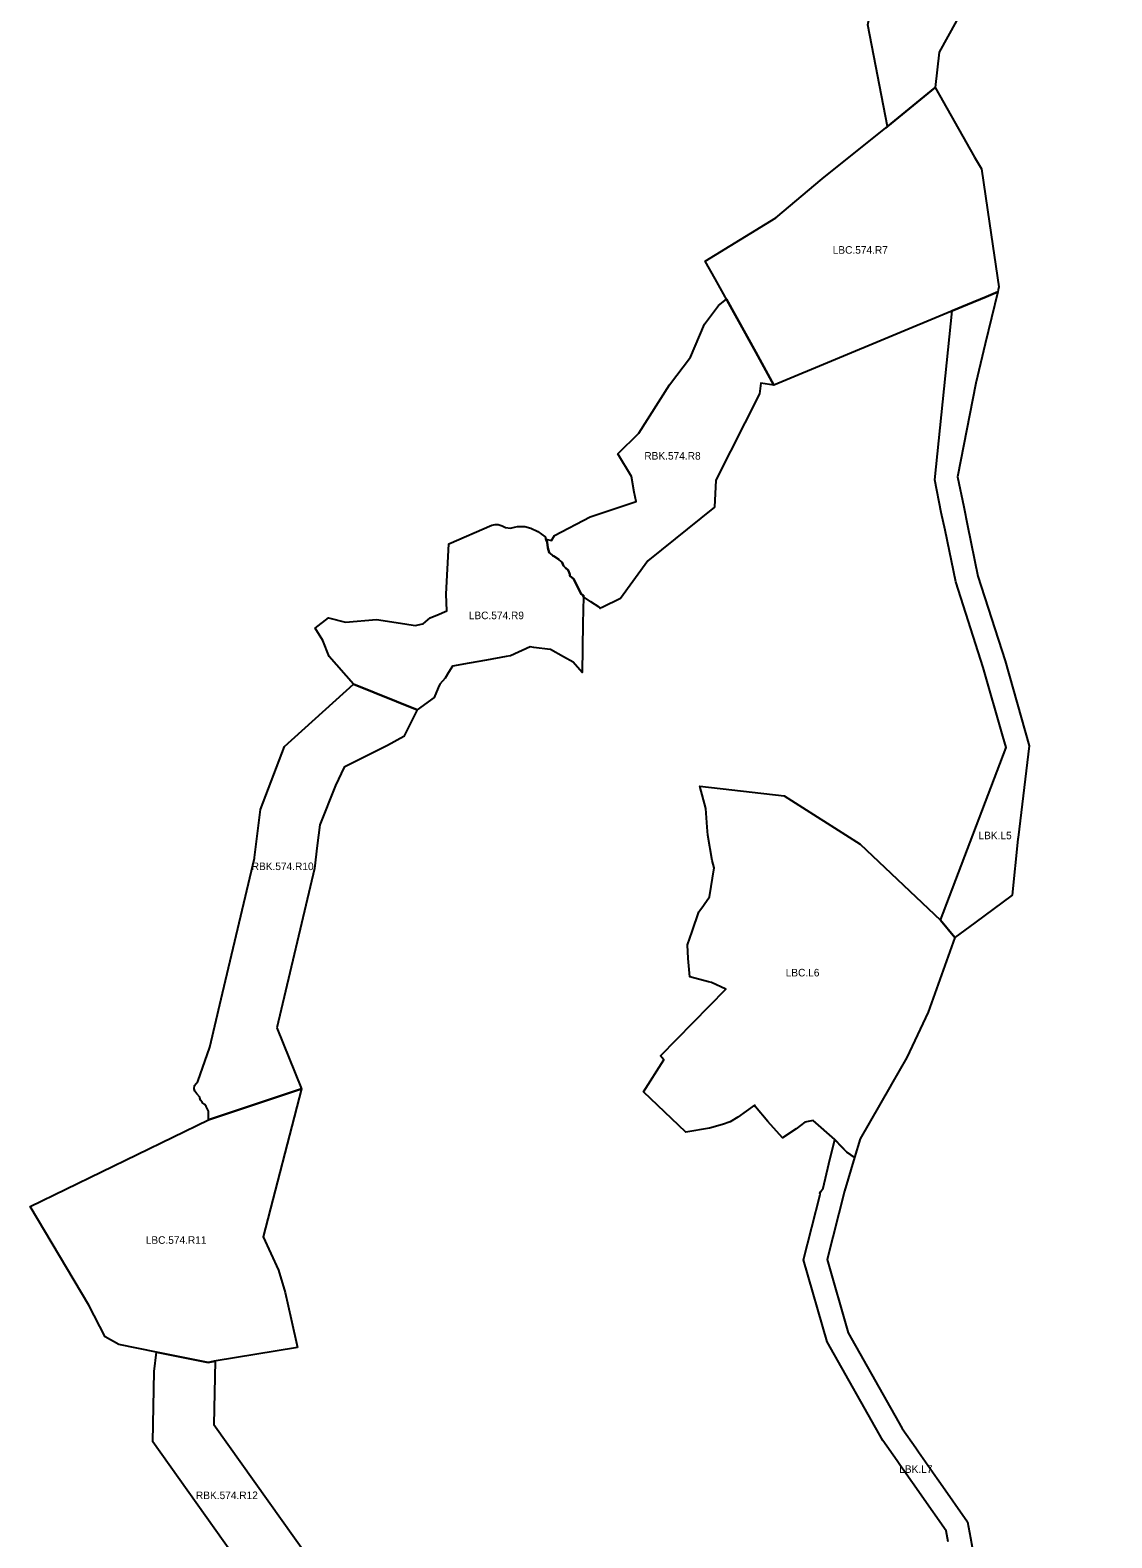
# Model space of a CAD drawing. Extents: x -450188 to -432919, y -1130252 to -1121189.
# Drawn here: x -435713 to -434285, y -1125455 to -1123464 of the extents above; entities that cross this region are included whole.
import ezdxf

# ---------------------------------------------------------------- set-up
doc = ezdxf.new("R2010")
doc.units = 0
for name, color, linetype in [('Vrstva 31', 7, 'Continuous'), ('Vrstva 32', 7, 'Continuous'), ('Vrstva 33', 7, 'Continuous'), ('Vrstva 36', 7, 'Continuous')]:
    doc.layers.add(name, color=color, linetype=linetype)

msp = doc.modelspace()

# ---------------------------------------------------------------- linework, layer by layer
at = {"layer": 'Vrstva 31'}
for p, q in [((-434518, -1123539.7), (-434580.6, -1123591.5)), ((-435286, -1124327.5), (-435201.7, -1124361.3)), ((-435546.1, -1125209.4), (-435477.7, -1125222.9))]:
    msp.add_line(p, q, dxfattribs=at)
for points in [[(-434363.9, -1123020.8), (-434324.5, -1123013.7), (-434284.6, -1123005.4), (-434295.7, -1123018.7), (-434299.7, -1123028.1), (-434301.1, -1123031.3), (-434304.3, -1123038.5), (-434314.4, -1123051.7), (-434320.8, -1123078.5), (-434332, -1123096.3), (-434354, -1123131.2), (-434377.2, -1123169.1), (-434389.6, -1123189.4), (-434412.9, -1123227.4), (-434449.8, -1123301), (-434458.9, -1123351.3), (-434471.9, -1123405.2), (-434478.2, -1123431.2), (-434512.4, -1123493.4), (-434518, -1123539.7)], [(-434580.6, -1123591.5), (-434606.8, -1123457.2), (-434543.2, -1123160.2), (-434507.9, -1123124.6), (-434478.5, -1123094.9), (-434447.2, -1123063.3), (-434413.4, -1123029.2)], [(-435387.2, -1124781.1), (-435354.5, -1124861.6), (-435477.4, -1124902.8), (-435477.4, -1124891.1), (-435480.1, -1124885), (-435482.1, -1124882.6), (-435485.2, -1124880.1), (-435485.6, -1124879.6), (-435487.6, -1124876.7), (-435488.5, -1124873.7), (-435488.8, -1124872.7), (-435492.5, -1124868.4), (-435495.1, -1124865), (-435496, -1124861.8), (-435495.5, -1124857.5), (-435491.3, -1124852.1), (-435475.5, -1124806.7), (-435460.4, -1124743), (-435458.7, -1124735.5), (-435416.6, -1124557.3), (-435416.4, -1124556.6), (-435408.4, -1124493), (-435376.7, -1124410), (-435286, -1124327.5)], [(-435201.7, -1124361.3), (-435219.3, -1124396.7), (-435241, -1124408.4), (-435298, -1124437.1), (-435309.5, -1124461.4), (-435330.3, -1124513.2), (-435333.8, -1124540.7), (-435337.5, -1124570.8), (-435387.2, -1124781.1)], [(-435477.7, -1125222.9), (-435468.6, -1125221.4), (-435470.4, -1125304.9), (-435345.1, -1125480.7), (-435258.9, -1125531.3), (-435353.4, -1125573.9), (-435398.3, -1125542.3), (-435550.8, -1125327.8), (-435548.9, -1125234.9), (-435546.1, -1125209.4)]]:
    msp.add_lwpolyline(points, dxfattribs=at)
msp.add_lwpolyline([(-435031.7, -1124136), (-435024.3, -1124138.1), (-435020.3, -1124131.1), (-434973.2, -1124106.6), (-434912.7, -1124086.2), (-434915.1, -1124074.2), (-434918.7, -1124053.4), (-434936.9, -1124023.5), (-434909, -1123996.3), (-434868.8, -1123932.3), (-434841, -1123895.9), (-434822.5, -1123852.2), (-434804, -1123827.8), (-434793.3, -1123819.1), (-434754.4, -1123889.2), (-434730.8, -1123932.7), (-434748, -1123930.1), (-434749.6, -1123944.2), (-434807.3, -1124058.1), (-434809.2, -1124093.7), (-434897, -1124164.8), (-434933.1, -1124214.3), (-434957.5, -1124226.2), (-434959.7, -1124227.3), (-434960.3, -1124227.6), (-434961.4, -1124225.8), (-434972.3, -1124218.8), (-434982.2, -1124212.3), (-434983, -1124209.5), (-434984.6, -1124209), (-434995.4, -1124188.5), (-435000.3, -1124184.4), (-435000.3, -1124182.2), (-435002.4, -1124177.2), (-435005.9, -1124174.1), (-435008.4, -1124171.3), (-435010.1, -1124166.9), (-435015.3, -1124162.7), (-435021.5, -1124158.7), (-435027.6, -1124153.9), (-435029.4, -1124147.6), (-435030.2, -1124139.9)], close=True, dxfattribs=at)
at = {"layer": 'Vrstva 32'}
for p, q in [((-434580.6, -1123591.5), (-434518, -1123539.7)), ((-434583, -1123593.5), (-434580.6, -1123591.6)), ((-434580.6, -1123591.6), (-434580.6, -1123591.5)), ((-435005.9, -1124174.1), (-435002.4, -1124177.2)), ((-435002.4, -1124177.2), (-435000.6, -1124181.5)), ((-435000.6, -1124181.5), (-435000.3, -1124182.2)), ((-434984.6, -1124209), (-434983, -1124209.5)), ((-434983, -1124209.5), (-434982, -1124210)), ((-435201.7, -1124361.3), (-435286, -1124327.5)), ((-434511, -1124639.1), (-434491.8, -1124662.2)), ((-434643.1, -1124936.6), (-434650.5, -1124928.8))]:
    msp.add_line(p, q, dxfattribs=at)
for points in [[(-434518, -1123539.7), (-434465.7, -1123631.7), (-434456.8, -1123647.3), (-434445.9, -1123719.6), (-434433.6, -1123802.9), (-434434.6, -1123807.1), (-434435.2, -1123809.7)], [(-434808.4, -1123792.6), (-434821.5, -1123769.2), (-434728.1, -1123712.1), (-434666.9, -1123660.3), (-434580.6, -1123591.5), (-434583, -1123593.5)], [(-434730.8, -1123932.7), (-434754.4, -1123889.2), (-434808.4, -1123792.6)], [(-434435.2, -1123809.7), (-434450.3, -1123816), (-434475.1, -1123826.3)], [(-434475.1, -1123826.3), (-434495.6, -1123834.8), (-434497.3, -1123835.5), (-434730.8, -1123932.7)], [(-435286, -1124327.5), (-435317.7, -1124291.1), (-435317.7, -1124290.9), (-435326.2, -1124270), (-435336.5, -1124253.5), (-435318.9, -1124240.1), (-435296.4, -1124245.8), (-435255.4, -1124242.4), (-435218.1, -1124247.9), (-435204.4, -1124249.9), (-435194.4, -1124248.1), (-435193.6, -1124247.9), (-435184.4, -1124240.2), (-435172.9, -1124235.2), (-435165.6, -1124231.9), (-435162.6, -1124230.6), (-435163.5, -1124208.7), (-435159.8, -1124142.3), (-435103, -1124117.7), (-435098.9, -1124116.8), (-435094.7, -1124116.8), (-435089.6, -1124118.6), (-435085, -1124120.7), (-435078.6, -1124121.5), (-435073.4, -1124120.2), (-435069.2, -1124119.6), (-435067.1, -1124119.3), (-435060.9, -1124119.3), (-435059.4, -1124119.3), (-435051.8, -1124121.6), (-435042.4, -1124126.2), (-435032.9, -1124132.9), (-435031.7, -1124136)], [(-435031.7, -1124136), (-435030.2, -1124139.9), (-435029.4, -1124147.6), (-435027.6, -1124153.9)], [(-435027.6, -1124153.9), (-435022.9, -1124157.8), (-435021.5, -1124158.7), (-435015.3, -1124162.7), (-435014.5, -1124163.4)], [(-435014.5, -1124163.4), (-435010.1, -1124166.9), (-435008.4, -1124171.3), (-435005.9, -1124174.1)], [(-435000.3, -1124182.2), (-435000.3, -1124184.4), (-434995.4, -1124188.5), (-434986.8, -1124204.8), (-434984.6, -1124209)], [(-434982, -1124210), (-434982.2, -1124212.3), (-434982.9, -1124247.3), (-434984.1, -1124312), (-434995.6, -1124298.7), (-435008.4, -1124291.3), (-435025.5, -1124282), (-435026.2, -1124281.9), (-435047.9, -1124279), (-435052.5, -1124278.4), (-435078.6, -1124290.1), (-435084.4, -1124291.1), (-435110.1, -1124295.7), (-435133.1, -1124299.7), (-435155.1, -1124303.6), (-435160.3, -1124312.1), (-435164.9, -1124319.5), (-435168.5, -1124323.6), (-435171.9, -1124327.6), (-435173.9, -1124332.2), (-435179.4, -1124345.3), (-435201.7, -1124361.3)], [(-434813.3, -1124721.6), (-434817.2, -1124720.6), (-434841.8, -1124713.9), (-434843.8, -1124689.7), (-434844.7, -1124671.9), (-434838.7, -1124654), (-434830, -1124628.1), (-434828.7, -1124626.3), (-434823.8, -1124619.6), (-434823, -1124618.6), (-434815.6, -1124608.4), (-434809.6, -1124570), (-434812.2, -1124560.4), (-434818, -1124527), (-434818.8, -1124516.3), (-434820.7, -1124491.5), (-434828.7, -1124462), (-434717, -1124475), (-434617, -1124538.6), (-434511, -1124639.1)], [(-434491.8, -1124662.2), (-434527.1, -1124760.6), (-434555.3, -1124820.5), (-434575.5, -1124855.6), (-434577.7, -1124859.5), (-434617, -1124927.6), (-434624.4, -1124952.6), (-434634.6, -1124945.5), (-434643.1, -1124936.6)], [(-434650.5, -1124928.8), (-434679, -1124903.6), (-434690.1, -1124905.6), (-434701.5, -1124914.4), (-434719.4, -1124926.6), (-434738.6, -1124905.1), (-434755.2, -1124885.6), (-434756.5, -1124883.3), (-434778.5, -1124899.2), (-434788.4, -1124905.3), (-434798.5, -1124908.7), (-434815.7, -1124913.6), (-434847.1, -1124919), (-434903, -1124865.8), (-434876.1, -1124823.7), (-434880.5, -1124818.2), (-434794, -1124730), (-434813.3, -1124721.6)]]:
    msp.add_lwpolyline(points, dxfattribs=at)
msp.add_lwpolyline([(-435359.9, -1125203.1), (-435469.8, -1125221.5), (-435477.7, -1125222.9), (-435546.1, -1125209.4), (-435595.6, -1125199.5), (-435613.5, -1125189), (-435635.3, -1125147.3), (-435712.7, -1125017), (-435477.4, -1124902.8), (-435354.5, -1124861.6), (-435405.2, -1125057), (-435384.8, -1125101), (-435375.8, -1125130.7), (-435368.1, -1125165.7)], close=True, dxfattribs=at)
at = {"layer": 'Vrstva 33'}
for p, q in [((-434475.1, -1123826.3), (-434450.3, -1123816)), ((-434450.3, -1123816), (-434435.2, -1123809.7)), ((-434495.6, -1123834.8), (-434475.1, -1123826.3)), ((-434650.5, -1124928.8), (-434650.5, -1124928.8)), ((-434650.5, -1124928.8), (-434634.6, -1124945.5)), ((-434634.6, -1124945.5), (-434624.4, -1124952.6))]:
    msp.add_line(p, q, dxfattribs=at)
for points in [[(-434435.2, -1123809.7), (-434451.7, -1123878.3), (-434464.2, -1123930.2), (-434488.3, -1124053.7), (-434480.2, -1124093.6), (-434475.1, -1124118.3), (-434461.6, -1124184.9), (-434425.6, -1124296.7), (-434393.8, -1124408.9), (-434408.3, -1124529.8), (-434408.7, -1124532.3), (-434416.1, -1124606.3), (-434465.6, -1124642.8)], [(-434511, -1124639.1), (-434424.3, -1124411.3), (-434428.5, -1124396.4), (-434454.3, -1124305.4), (-434490.6, -1124192.5), (-434504.5, -1124124.3), (-434509.8, -1124101.1), (-434518.1, -1124058), (-434495.6, -1123834.8)], [(-434465.6, -1124642.8), (-434491.8, -1124662.2), (-434511, -1124639.1)], [(-434500.9, -1125459.8), (-434503.5, -1125445.3), (-434535.4, -1125399.6), (-434539.6, -1125393.6), (-434564.5, -1125358), (-434567.9, -1125353), (-434586.8, -1125326), (-434660.3, -1125195.8), (-434691.7, -1125087.6), (-434669.7, -1125001.3), (-434670.1, -1124999.6), (-434668.7, -1124997.5), (-434665.8, -1124992.9), (-434658.2, -1124960.8), (-434650.5, -1124928.8)], [(-434624.4, -1124952.6), (-434637.7, -1124997.1), (-434660.6, -1125087.1), (-434632.5, -1125184.1), (-434561.4, -1125310), (-434543.3, -1125335.9), (-434539.8, -1125340.8), (-434515, -1125376.4), (-434510.8, -1125382.4), (-434475.1, -1125433.5), (-434471.4, -1125454.4), (-434462.5, -1125503.9)]]:
    msp.add_lwpolyline(points, dxfattribs=at)

# ---------------------------------------------------------------- texts
at = {"layer": 'Vrstva 36'}
for s, p in [('LBC.574.R7', (-434653.1, -1123759.3)), ('RBK.574.R8', (-434901.8, -1124031.1)), ('LBC.574.R9', (-435133.6, -1124241.8)), ('LBK.L5', (-434460.7, -1124532.3)), ('RBK.574.R10', (-435420.2, -1124573)), ('LBC.L6', (-434715.2, -1124713.4)), ('LBC.574.R11', (-435560.1, -1125066.4)), ('LBK.L7', (-434565.3, -1125368.8)), ('RBK.574.R12', (-435493.8, -1125403.4))]:
    msp.add_text(s, height=10, dxfattribs=at).set_placement(p)

doc.saveas('drawing.dxf')
